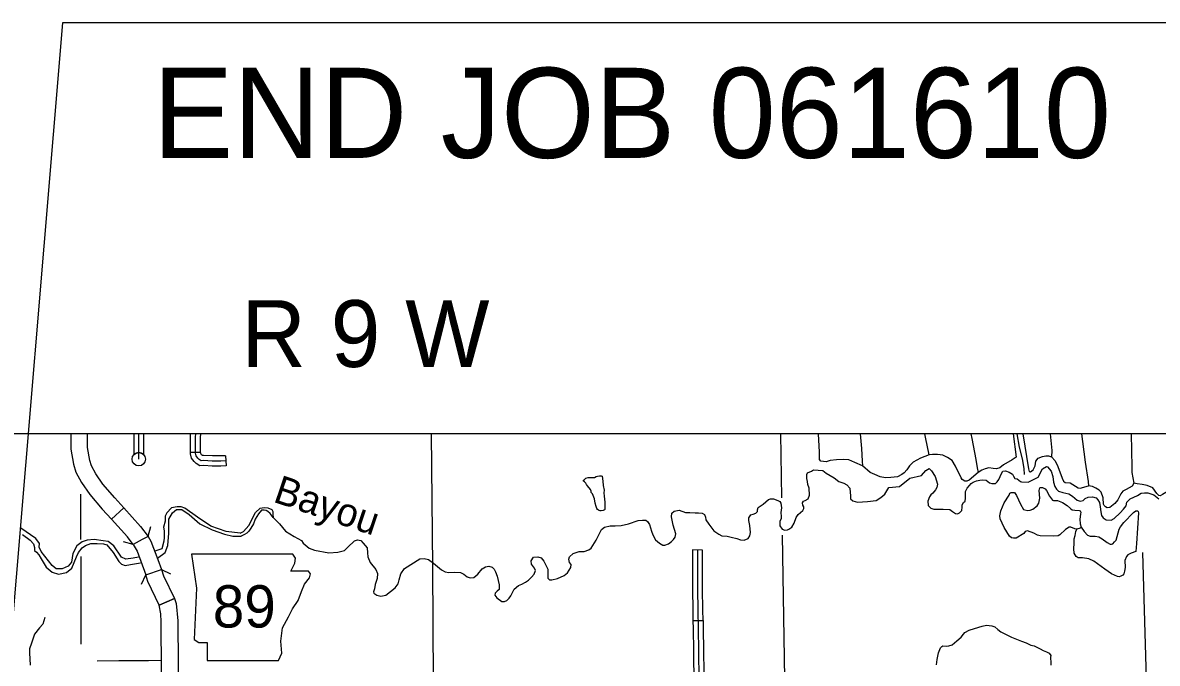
# Model space of a CAD drawing. Extents: x 1127717 to 1741049, y 2026793 to 2244711.
# Drawn here: x 1315678 to 1332669, y 2108505 to 2118098 of the extents above; entities that cross this region are included whole.
import ezdxf

# ---------------------------------------------------------------- set-up
doc = ezdxf.new("R2010")
doc.units = 0
for name, color, linetype in [('1', 7, 'Continuous'), ('10', 7, 'Continuous'), ('21', 7, 'Continuous'), ('31', 7, 'Continuous'), ('32', 7, 'Continuous'), ('35', 7, 'Continuous'), ('37', 7, 'Continuous'), ('43', 7, 'Continuous'), ('5', 7, 'Continuous'), ('R_Draft', 7, 'Continuous')]:
    doc.layers.add(name, color=color, linetype=linetype)

msp = doc.modelspace()

# ---------------------------------------------------------------- linework, layer by layer
at = {"layer": '1'}
msp.add_lwpolyline([(1349634, 2111942), (1278363, 2111942), (1278363, 2066677), (1349634, 2066677)], close=True, dxfattribs=at)
at = {"layer": '10'}
for p, q in [((1317008, 2110665), (1317192, 2110834)), ((1317008, 2110665), (1317008, 2110665)), ((1317555, 2110405), (1317466, 2110357)), ((1317521, 2109827), (1317757, 2109908)), ((1317952, 2109473), (1317720, 2109375)), ((1317720, 2109375), (1317952, 2109473))]:
    msp.add_line(p, q, dxfattribs=at)
for points in [[(1316399, 2111942), (1316401, 2111711), (1316441, 2111488), (1316473, 2111369), (1316558, 2111210), (1316682, 2111033), (1316870, 2110815), (1317008, 2110665)], [(1317192, 2110834), (1317057, 2110981), (1316880, 2111186), (1316771, 2111341), (1316707, 2111461), (1316686, 2111542), (1316651, 2111734), (1316649, 2111942)], [(1317008, 2110665), (1317192, 2110834)], [(1317466, 2110357), (1317332, 2110282), (1317247, 2110396), (1317008, 2110665)], [(1317192, 2110834), (1317443, 2110552), (1317555, 2110405)], [(1317555, 2110405), (1317595, 2110333), (1317703, 2110059), (1317757, 2109908)], [(1317332, 2110282), (1317392, 2110186), (1317521, 2109827)], [(1317720, 2109375), (1317552, 2109729), (1317521, 2109827)], [(1317757, 2109908), (1317786, 2109816), (1317952, 2109473)], [(1317742, 2100882), (1317776, 2101118), (1317784, 2101251), (1317794, 2103256), (1317752, 2109126), (1317745, 2109246), (1317720, 2109375)], [(1317952, 2109473), (1317974, 2109401), (1318002, 2109141), (1318044, 2103256), (1318034, 2101243), (1318025, 2101093), (1317989, 2100844)]]:
    msp.add_lwpolyline(points, dxfattribs=at)
at = {"layer": '21'}
msp.add_lwpolyline([(1318205, 2110138), (1318281, 2109631), (1318247, 2108861), (1318315, 2108818), (1318442, 2108818), (1318442, 2108548), (1319508, 2108548), (1319558, 2108658), (1319542, 2108835), (1319567, 2109038), (1319660, 2109199), (1319719, 2109318), (1319804, 2109444), (1319855, 2109580), (1319897, 2109690), (1319973, 2109783), (1319990, 2109842), (1319956, 2109884), (1319694, 2109884), (1319753, 2110003), (1319762, 2110079), (1319726, 2110137)], close=True, dxfattribs=at)
at = {"layer": '31'}
for p, q in [((1325859, 2110201), (1325709, 2110203)), ((1325716, 2109144), (1325866, 2109148))]:
    msp.add_line(p, q, dxfattribs=at)
for points in [[(1317344, 2111942), (1317342, 2111668), (1317342, 2111627)], [(1317417, 2111561), (1317417, 2111668), (1317419, 2111942)], [(1317492, 2111627), (1317492, 2111668), (1317494, 2111942)], [(1325709, 2110203), (1325707, 2109932), (1325709, 2109674)], [(1325784, 2110202), (1325782, 2109932), (1325784, 2109615), (1325787, 2109301), (1325794, 2109022), (1325799, 2108693), (1325806, 2108263), (1325811, 2107746), (1325820, 2107351)], [(1325859, 2109675), (1325857, 2109932), (1325859, 2110201)], [(1325709, 2109674), (1325709, 2109614), (1325712, 2109300), (1325716, 2109144)], [(1325866, 2109148), (1325862, 2109303), (1325859, 2109615), (1325859, 2109675)], [(1325716, 2109144), (1325719, 2109020), (1325724, 2108692), (1325725, 2108617)], [(1325866, 2109148), (1325869, 2109023), (1325874, 2108694), (1325875, 2108620)], [(1317756, 2108549), (1317563, 2108543), (1317120, 2108541), (1316791, 2108538)], [(1325725, 2108617), (1325731, 2108262), (1325733, 2108090)], [(1325875, 2108620), (1325881, 2108264), (1325883, 2108091)]]:
    msp.add_lwpolyline(points, dxfattribs=at)
msp.add_circle((1317417, 2111561), 100, dxfattribs=at)
msp.add_arc((1317417, 2111561), 100, 41.4099, 138.5901, dxfattribs=at)
at = {"layer": '32'}
for p, q in [((1318339, 2111662), (1318189, 2111662)), ((1318716, 2111612), (1318723, 2111463))]:
    msp.add_line(p, q, dxfattribs=at)
for points in [[(1318189, 2111662), (1318189, 2111703), (1318189, 2111823), (1318189, 2111894), (1318193, 2111942)], [(1318719, 2111537), (1318643, 2111534), (1318517, 2111534), (1318387, 2111541), (1318351, 2111537), (1318322, 2111555), (1318300, 2111577), (1318275, 2111610), (1318264, 2111649), (1318264, 2111703), (1318264, 2111823), (1318264, 2111891), (1318269, 2111942)], [(1318339, 2111662), (1318339, 2111703), (1318339, 2111823), (1318339, 2111888), (1318344, 2111942)], [(1318723, 2111463), (1318645, 2111459), (1318515, 2111459), (1318389, 2111466), (1318333, 2111460), (1318275, 2111496), (1318244, 2111527), (1318207, 2111575), (1318189, 2111639), (1318189, 2111662)], [(1318716, 2111612), (1318642, 2111609), (1318519, 2111609), (1318385, 2111616), (1318369, 2111615), (1318357, 2111627), (1318344, 2111644), (1318339, 2111659), (1318339, 2111662)], [(1316012, 2109193), (1315978, 2109091), (1315930, 2109035), (1315857, 2108943), (1315809, 2108805), (1315782, 2108720), (1315780, 2108662), (1315789, 2108476)]]:
    msp.add_lwpolyline(points, dxfattribs=at)
at = {"layer": '35'}
for points in [[(1327596, 2111934), (1327595, 2111942)], [(1330510, 2111942), (1330558, 2111592), (1330496, 2111551), (1330365, 2111475), (1330313, 2111433), (1330261, 2111419), (1330210, 2111423), (1330144, 2111430), (1330092, 2111419), (1330040, 2111399), (1329985, 2111364), (1329851, 2111247), (1329816, 2111233), (1329788, 2111233), (1329747, 2111257), (1329730, 2111281), (1329647, 2111457), (1329595, 2111540), (1329526, 2111585), (1329457, 2111620), (1329378, 2111630), (1329305, 2111630), (1329253, 2111627), (1329125, 2111578), (1329015, 2111516), (1328956, 2111464), (1328918, 2111402), (1328880, 2111357), (1328842, 2111330), (1328777, 2111295), (1328680, 2111285), (1328601, 2111281), (1328518, 2111299), (1328438, 2111333), (1328369, 2111364), (1328255, 2111464), (1328141, 2111513), (1328048, 2111551), (1327976, 2111558), (1327865, 2111551), (1327772, 2111544), (1327710, 2111520), (1327630, 2111530), (1327610, 2111558), (1327613, 2111672), (1327596, 2111934)], [(1328220, 2111942), (1328238, 2111723), (1328252, 2111533), (1328255, 2111464)], [(1329253, 2111627), (1329198, 2111893), (1329190, 2111942)], [(1329879, 2111942), (1329892, 2111872), (1329951, 2111558), (1329971, 2111433), (1329985, 2111364)], [(1330656, 2111942), (1330740, 2111415), (1330750, 2111377), (1330768, 2111372), (1330811, 2111402), (1330840, 2111461), (1330852, 2111530), (1330886, 2111576), (1330952, 2111601), (1331000, 2111612), (1331041, 2111609), (1331085, 2111594), (1331141, 2111535), (1331182, 2111451), (1331246, 2111275), (1331263, 2111231), (1331291, 2111211), (1331366, 2111206), (1331406, 2111180), (1331483, 2111131), (1331516, 2111129), (1331641, 2111162)], [(1331065, 2111942), (1331092, 2111691), (1331085, 2111594)], [(1331532, 2111942), (1331547, 2111826), (1331590, 2111515), (1331634, 2111226), (1331641, 2111162)], [(1332276, 2111942), (1332288, 2111442)], [(1332866, 2111942), (1332889, 2111370), (1332902, 2111178), (1332892, 2111137), (1332856, 2111099), (1332749, 2111033), (1332710, 2111010), (1332692, 2111015), (1332664, 2111048), (1332603, 2111130), (1332516, 2111165), (1332442, 2111183), (1332366, 2111194), (1332318, 2111200)], [(1325459, 2110442), (1325417, 2110571), (1325394, 2110699), (1325397, 2110751), (1325436, 2110782), (1325509, 2110796), (1325606, 2110762), (1325670, 2110762), (1325748, 2110757), (1325798, 2110757), (1325853, 2110755), (1325887, 2110733), (1325905, 2110694), (1325909, 2110651), (1325951, 2110587), (1326026, 2110487), (1326104, 2110436), (1326148, 2110411), (1326226, 2110406), (1326287, 2110392), (1326374, 2110376), (1326428, 2110354), (1326484, 2110350), (1326542, 2110373), (1326565, 2110411), (1326576, 2110464), (1326565, 2110567), (1326554, 2110645), (1326554, 2110685), (1326582, 2110729), (1326615, 2110740), (1326657, 2110754), (1326681, 2110779), (1326681, 2110805), (1326693, 2110836), (1326766, 2110886), (1326847, 2110956), (1326875, 2110969), (1326922, 2110969), (1326988, 2110942), (1327019, 2110928), (1327034, 2110903), (1327044, 2110833), (1327030, 2110763), (1327038, 2110701), (1327038, 2110674), (1327019, 2110630), (1327017, 2110591), (1327019, 2110563), (1327050, 2110512), (1327092, 2110498), (1327130, 2110501), (1327153, 2110514), (1327197, 2110545), (1327230, 2110602), (1327261, 2110690), (1327290, 2110733), (1327325, 2110762), (1327361, 2110793), (1327377, 2110824), (1327375, 2110849), (1327361, 2110872), (1327355, 2110907), (1327372, 2110933), (1327397, 2110941), (1327441, 2110970), (1327461, 2111023), (1327456, 2111126), (1327436, 2111184), (1327431, 2111228), (1327422, 2111270), (1327422, 2111334), (1327431, 2111359), (1327489, 2111384), (1327520, 2111401), (1327590, 2111399), (1327661, 2111390), (1327712, 2111354), (1327829, 2111281), (1327899, 2111229), (1327977, 2111203), (1328019, 2111175), (1328066, 2111129), (1328071, 2111062), (1328074, 2111017), (1328077, 2110969), (1328110, 2110939), (1328180, 2110917), (1328328, 2110928), (1328459, 2110941), (1328528, 2110987), (1328590, 2111037), (1328649, 2111137)], [(1328649, 2111137), (1328809, 2111153), (1328961, 2111279), (1329138, 2111317), (1329201, 2111393), (1329255, 2111422), (1329290, 2111387)], [(1329290, 2111387), (1329345, 2111301), (1329378, 2111189), (1329367, 2111139), (1329349, 2111100), (1329309, 2111054), (1329276, 2111028), (1329259, 2110995), (1329231, 2110931), (1329236, 2110870), (1329279, 2110828), (1329321, 2110813), (1329387, 2110814), (1329462, 2110813), (1329561, 2110808), (1329600, 2110777), (1329647, 2110749), (1329679, 2110742), (1329709, 2110756), (1329740, 2110792), (1329749, 2110844), (1329749, 2110877), (1329765, 2110912), (1329790, 2110934), (1329798, 2110976), (1329798, 2110998), (1329799, 2111079), (1329823, 2111128), (1329855, 2111165), (1329883, 2111196), (1329912, 2111215), (1329963, 2111235), (1330014, 2111245), (1330050, 2111251), (1330105, 2111245), (1330156, 2111206), (1330192, 2111196), (1330244, 2111198), (1330273, 2111221), (1330298, 2111256), (1330336, 2111348), (1330356, 2111380), (1330396, 2111388), (1330449, 2111368), (1330501, 2111335), (1330518, 2111309), (1330538, 2111274), (1330571, 2111267)], [(1330571, 2111267), (1330619, 2111226), (1330635, 2111223), (1330733, 2111216), (1330885, 2111292), (1330949, 2111419), (1331010, 2111453)], [(1331010, 2111453), (1331024, 2111445), (1331080, 2111382), (1331103, 2111303), (1331115, 2111215), (1331134, 2111150), (1331159, 2111110), (1331190, 2111084), (1331255, 2111061), (1331343, 2111042), (1331397, 2111005), (1331469, 2110949), (1331515, 2110933), (1331557, 2110945), (1331590, 2110973), (1331634, 2110994), (1331697, 2110998), (1331755, 2110982), (1331778, 2110954), (1331802, 2110912), (1331816, 2110849), (1331823, 2110775), (1331832, 2110719), (1331860, 2110684), (1331904, 2110651), (1331976, 2110647), (1332021, 2110675), (1332111, 2110756), (1332162, 2110814), (1332202, 2110863), (1332214, 2110919), (1332265, 2110966), (1332374, 2111019), (1332430, 2111054), (1332479, 2111059), (1332526, 2111056), (1332526, 2111056), (1332600, 2111031), (1332616, 2111029), (1332691, 2110970)], [(1332288, 2111442), (1332290, 2111364), (1332318, 2111200)], [(1324358, 2111306), (1324364, 2111234), (1324371, 2111165), (1324384, 2111096), (1324383, 2111056), (1324386, 2111008), (1324398, 2110920), (1324397, 2110837), (1324397, 2110809), (1324389, 2110802), (1324369, 2110794), (1324343, 2110789), (1324325, 2110789), (1324311, 2110792), (1324299, 2110799), (1324287, 2110809), (1324274, 2110822), (1324265, 2110853), (1324251, 2110905), (1324239, 2110966), (1324209, 2111043), (1324192, 2111064), (1324192, 2111082), (1324180, 2111109), (1324137, 2111163), (1324121, 2111180), (1324110, 2111200), (1324101, 2111211), (1324089, 2111221), (1324077, 2111233), (1324077, 2111245), (1324090, 2111258)], [(1324090, 2111258), (1324112, 2111276), (1324146, 2111288), (1324196, 2111287), (1324219, 2111287), (1324239, 2111289), (1324265, 2111300), (1324287, 2111308), (1324316, 2111312), (1324343, 2111312), (1324358, 2111306)], [(1332318, 2111200), (1332292, 2111155), (1332205, 2111107), (1332151, 2111084), (1332123, 2111040), (1332077, 2110953), (1332031, 2110900), (1331960, 2110839), (1331921, 2110831), (1331896, 2110846), (1331875, 2110867), (1331865, 2110890), (1331858, 2110984), (1331829, 2111066), (1331799, 2111096), (1331748, 2111127), (1331699, 2111150), (1331641, 2111162)], [(1331530, 2110543), (1331514, 2110529), (1331463, 2110512), (1331435, 2110519), (1331375, 2110543), (1331349, 2110543), (1331294, 2110509), (1331212, 2110430), (1331185, 2110414), (1331115, 2110410), (1330917, 2110412), (1330877, 2110424), (1330822, 2110452), (1330724, 2110486), (1330690, 2110476), (1330671, 2110449), (1330558, 2110380), (1330518, 2110380), (1330484, 2110383), (1330456, 2110408), (1330375, 2110537), (1330314, 2110669), (1330311, 2110713), (1330325, 2110786), (1330378, 2110909), (1330450, 2111021), (1330463, 2111050), (1330480, 2111060), (1330501, 2111064), (1330530, 2111060), (1330562, 2111016), (1330619, 2110889), (1330667, 2110810), (1330686, 2110801), (1330732, 2110794), (1330764, 2110796), (1330803, 2110811), (1330869, 2110861), (1330895, 2110902), (1330910, 2110976), (1330901, 2111091), (1330904, 2111112), (1330908, 2111131), (1330918, 2111136), (1330948, 2111138), (1330989, 2111119), (1331009, 2111092), (1331057, 2111008), (1331100, 2110947), (1331117, 2110943), (1331174, 2110943), (1331252, 2110915), (1331321, 2110869), (1331368, 2110821), (1331396, 2110803), (1331436, 2110796), (1331498, 2110794), (1331515, 2110786), (1331524, 2110770), (1331518, 2110736)], [(1318937, 2110455), (1318724, 2110476), (1318498, 2110560), (1318298, 2110693), (1318106, 2110827), (1318052, 2110848), (1317993, 2110848), (1317906, 2110831), (1317835, 2110760), (1317810, 2110706), (1317810, 2110631), (1317789, 2110543), (1317797, 2110489), (1317797, 2110439), (1317797, 2110389), (1317793, 2110336), (1317761, 2110218), (1317659, 2110183)], [(1318937, 2110455), (1318986, 2110476), (1319066, 2110568), (1319164, 2110764), (1319236, 2110826), (1319294, 2110838), (1319351, 2110834), (1319410, 2110808), (1319426, 2110776), (1319422, 2110739), (1319427, 2110688)], [(1317696, 2110077), (1317814, 2110164), (1317852, 2110270), (1317865, 2110455), (1317865, 2110505), (1317865, 2110576), (1317865, 2110664), (1317923, 2110760), (1317981, 2110806), (1318060, 2110810), (1318173, 2110731), (1318331, 2110593), (1318515, 2110505)], [(1319427, 2110688), (1319382, 2110750), (1319351, 2110780), (1319324, 2110795), (1319293, 2110800), (1319253, 2110796), (1319208, 2110741), (1319161, 2110662), (1319136, 2110594), (1319096, 2110529), (1319064, 2110482), (1319034, 2110452), (1319001, 2110433), (1318949, 2110409)], [(1319427, 2110688), (1319526, 2110594), (1319612, 2110482), (1319745, 2110401), (1319854, 2110346), (1319877, 2110305), (1319966, 2110229), (1320046, 2110201), (1320261, 2110159), (1320395, 2110171), (1320498, 2110195), (1320546, 2110245), (1320648, 2110338), (1320693, 2110354), (1320741, 2110343), (1320778, 2110304), (1320838, 2110232), (1320841, 2110160), (1320849, 2110100), (1320883, 2110015), (1320967, 2109911), (1320991, 2109850), (1320984, 2109777), (1320957, 2109684), (1320945, 2109620), (1320931, 2109573), (1320936, 2109554), (1320979, 2109526)], [(1331530, 2110543), (1331575, 2110478), (1331625, 2110424), (1331666, 2110410), (1331737, 2110408), (1331792, 2110400), (1331842, 2110369), (1331921, 2110312), (1331961, 2110289), (1331983, 2110289), (1332002, 2110295), (1332029, 2110322), (1332054, 2110349), (1332097, 2110515), (1332117, 2110550), (1332166, 2110613), (1332311, 2110763), (1332348, 2110789), (1332371, 2110790), (1332382, 2110780), (1332386, 2110757), (1332358, 2110299), (1332348, 2110180), (1332278, 2110154), (1332227, 2110130), (1332206, 2110105), (1332185, 2110046), (1332188, 2109940), (1332178, 2109886), (1332168, 2109846), (1332154, 2109825), (1332124, 2109809), (1332100, 2109801), (1332071, 2109802), (1331982, 2109843), (1331886, 2109912), (1331720, 2110036), (1331643, 2110069), (1331549, 2110082), (1331486, 2110083), (1331454, 2110106), (1331425, 2110154), (1331420, 2110218), (1331422, 2110306), (1331423, 2110369), (1331439, 2110418), (1331450, 2110478), (1331463, 2110512)], [(1331518, 2110736), (1331508, 2110662), (1331513, 2110593), (1331530, 2110543)], [(1317410, 2110096), (1317330, 2110077), (1317224, 2110065), (1317156, 2110096), (1317044, 2110264), (1316958, 2110329), (1316884, 2110338), (1316750, 2110359), (1316646, 2110347), (1316571, 2110322), (1316491, 2110263), (1316429, 2110151), (1316408, 2110017), (1316358, 2109958), (1316270, 2109921), (1316178, 2109917), (1316120, 2109971), (1315953, 2110180), (1315924, 2110242), (1315928, 2110301), (1315874, 2110376), (1315652, 2110526)], [(1318515, 2110505), (1318699, 2110439), (1318824, 2110409), (1318903, 2110409), (1318949, 2110409)], [(1320979, 2109526), (1321040, 2109512), (1321115, 2109526), (1321257, 2109635), (1321302, 2109696), (1321316, 2109757), (1321342, 2109843), (1321394, 2109922), (1321626, 2110069), (1321692, 2110075), (1321754, 2110060), (1321832, 2110002), (1321951, 2109904), (1322007, 2109872), (1322061, 2109865), (1322147, 2109868), (1322233, 2109865), (1322286, 2109841), (1322336, 2109799), (1322379, 2109784), (1322432, 2109788), (1322495, 2109837), (1322557, 2109918), (1322607, 2109950), (1322660, 2109958), (1322710, 2109944), (1322737, 2109913), (1322759, 2109876), (1322783, 2109810), (1322797, 2109746), (1322811, 2109682), (1322815, 2109638), (1322814, 2109612), (1322783, 2109584), (1322756, 2109556), (1322751, 2109525), (1322779, 2109486), (1322853, 2109431), (1322893, 2109429), (1322929, 2109447), (1322963, 2109478), (1322987, 2109514), (1323012, 2109567), (1323038, 2109615), (1323102, 2109668), (1323155, 2109691), (1323207, 2109720), (1323253, 2109748), (1323300, 2109793), (1323336, 2109837), (1323358, 2109893), (1323342, 2109927), (1323298, 2109991), (1323292, 2110041), (1323329, 2110092), (1323392, 2110097), (1323443, 2110086), (1323480, 2110036), (1323504, 2109993), (1323544, 2109915), (1323544, 2109880), (1323541, 2109841), (1323540, 2109779), (1323565, 2109757), (1323602, 2109757), (1323686, 2109777), (1323788, 2109819), (1323838, 2109860), (1323889, 2109941), (1323891, 2109982), (1323866, 2110016), (1323856, 2110063), (1323867, 2110100), (1323920, 2110147), (1324011, 2110180), (1324084, 2110181), (1324157, 2110202), (1324190, 2110230), (1324266, 2110348), (1324344, 2110507), (1324393, 2110545), (1324475, 2110563), (1324552, 2110563), (1324641, 2110570), (1324750, 2110595), (1324895, 2110643), (1324962, 2110648), (1325009, 2110648), (1325035, 2110627), (1325063, 2110585), (1325093, 2110485), (1325115, 2110429), (1325155, 2110354), (1325217, 2110303), (1325264, 2110275), (1325292, 2110273), (1325350, 2110294), (1325392, 2110329), (1325425, 2110359), (1325450, 2110393), (1325459, 2110442)], [(1315677, 2110434), (1315790, 2110347), (1315840, 2110293), (1315853, 2110238), (1315853, 2110192), (1315886, 2110167), (1315920, 2110130), (1315953, 2110071), (1316028, 2109946), (1316120, 2109871), (1316212, 2109837), (1316333, 2109862), (1316412, 2109929), (1316483, 2110100), (1316512, 2110163), (1316571, 2110234), (1316621, 2110267), (1316700, 2110301), (1316792, 2110301), (1316888, 2110293), (1316937, 2110278), (1317031, 2110164), (1317118, 2110027), (1317156, 2109990), (1317212, 2109971), (1317292, 2109984), (1317442, 2110009)], [(1329361, 2108483), (1329371, 2108564), (1329393, 2108661), (1329424, 2108734), (1329442, 2108756), (1329459, 2108764), (1329507, 2108761), (1329546, 2108764), (1329595, 2108781), (1329666, 2108842), (1329734, 2108898), (1329766, 2108942), (1329788, 2108964), (1329851, 2109000), (1329934, 2109027), (1330048, 2109063), (1330112, 2109076), (1330190, 2109068), (1330236, 2109049), (1330280, 2109010), (1330324, 2108976), (1330404, 2108934), (1330487, 2108898), (1330636, 2108837), (1330704, 2108812), (1330774, 2108776), (1330826, 2108764), (1330913, 2108722), (1330962, 2108695), (1331011, 2108676), (1331052, 2108656), (1331077, 2108622), (1331069, 2108598), (1331074, 2108505), (1331074, 2108478)]]:
    msp.add_lwpolyline(points, dxfattribs=at)
at = {"layer": '37'}
for points in [[(1317590, 2110549), (1317550, 2110404)], [(1317332, 2110282), (1317188, 2110322)], [(1317455, 2109692), (1317521, 2109827)], [(1317757, 2109908), (1317892, 2109842)]]:
    msp.add_lwpolyline(points, dxfattribs=at)
at = {"layer": '43'}
msp.add_lwpolyline([(1330682, 2111330), (1330674, 2111424), (1330649, 2111567), (1330608, 2111741), (1330570, 2111942)], dxfattribs=at)
at = {"layer": '5'}
for points in [[(1321795, 2111942), (1321817, 2109955), (1321828, 2107376)], [(1327025, 2111942), (1327041, 2110981)], [(1316544, 2111037), (1316546, 2110357)], [(1327050, 2110425), (1327099, 2107359)], [(1332449, 2110163), (1332522, 2107582)], [(1316547, 2110102), (1316551, 2108793)]]:
    msp.add_lwpolyline(points, dxfattribs=at)
at = {"layer": 'R_Draft'}
for p, q in [((1316276, 2118098), (1313952, 2090343)), ((1336713, 2118098), (1316276, 2118098))]:
    msp.add_line(p, q, dxfattribs=at)

# ---------------------------------------------------------------- texts
at = {"layer": '21'}
msp.add_text('89', height=633.6, dxfattribs=at).set_placement((1318525, 2109040))
at = {"layer": '35'}
msp.add_text('Bayou', height=422.4, rotation=341.2882, dxfattribs=at).set_placement((1319413, 2110928))
at = {"layer": 'R_Draft'}
for s, height, p in [('END JOB 061610', 1350, (1317626, 2116073)), ('R 9 W', 1000, (1318954, 2112942))]:
    msp.add_text(s, height=height, dxfattribs=at).set_placement(p)

doc.saveas('drawing.dxf')
